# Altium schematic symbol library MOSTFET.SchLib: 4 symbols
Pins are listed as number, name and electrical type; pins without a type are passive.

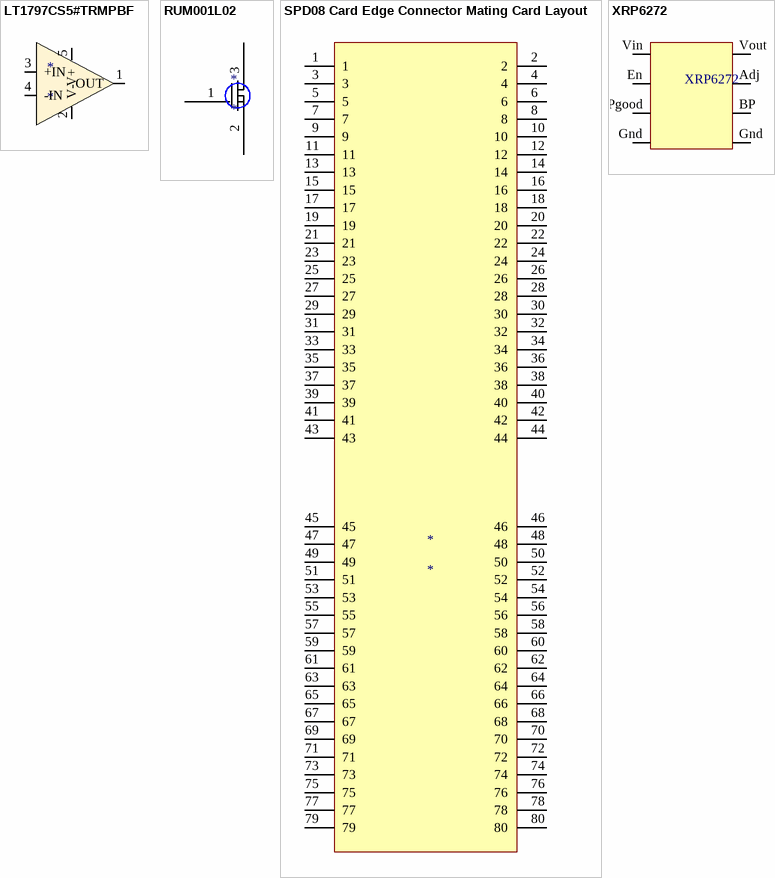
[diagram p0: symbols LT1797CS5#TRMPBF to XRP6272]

## LT1797CS5#TRMPBF
designator *
Buffer Op-Amp
footprint TSOT23-5 (5-LEAD plastic)
pins: 1 OUT, 2 V-, 3 +IN, 4 -IN, 5 V+

## RUM001L02
designator *  (mechanical)
Small Signal MOSFET
footprint SOT-723
pins: 1 Gate, 2 Source, 3 Drain

## SPD08 Card Edge Connector Mating Card Layout
designator *
footprint Card Edge Male
pins: 1, 2, 3, 4, 5, 6, 7, 8, 9, 10, 11, 12, 13, 14, 15, 16, 17, 18, 19, 20, 21, 22, 23, 24, 25, 26, 27, 28, 29, 30, 31, 32, 33, 34, 35, 36, 37, 38, 39, 40, 41, 42, 43, 44, 45, 46, 47, 48, 49, 50, 51, 52, 53, 54, 55, 56, 57, 58, 59, 60, 61, 62, 63, 64, 65, 66, 67, 68, 69, 70, 71, 72, 73, 74, 75, 76, 77, 78, 79, 80

## XRP6272
designator XRP6272
Low droput voltage regulator
footprint SOIC-8; pin to pad Adj>7 BP>6 En>2 Gnd>4 Pgood>3 Vin>1 Vout>8
pins: Adj 4, BP 6, En 1, Gnd 5, Gnd 8, Pgood 7, Vin 2, Vout 3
